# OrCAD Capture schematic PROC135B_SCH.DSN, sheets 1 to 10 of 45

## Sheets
1 03. LINKS TO KEY COLLATERS: title: LINKS TO KEY COLLATERALS AND FAQs; rev: B
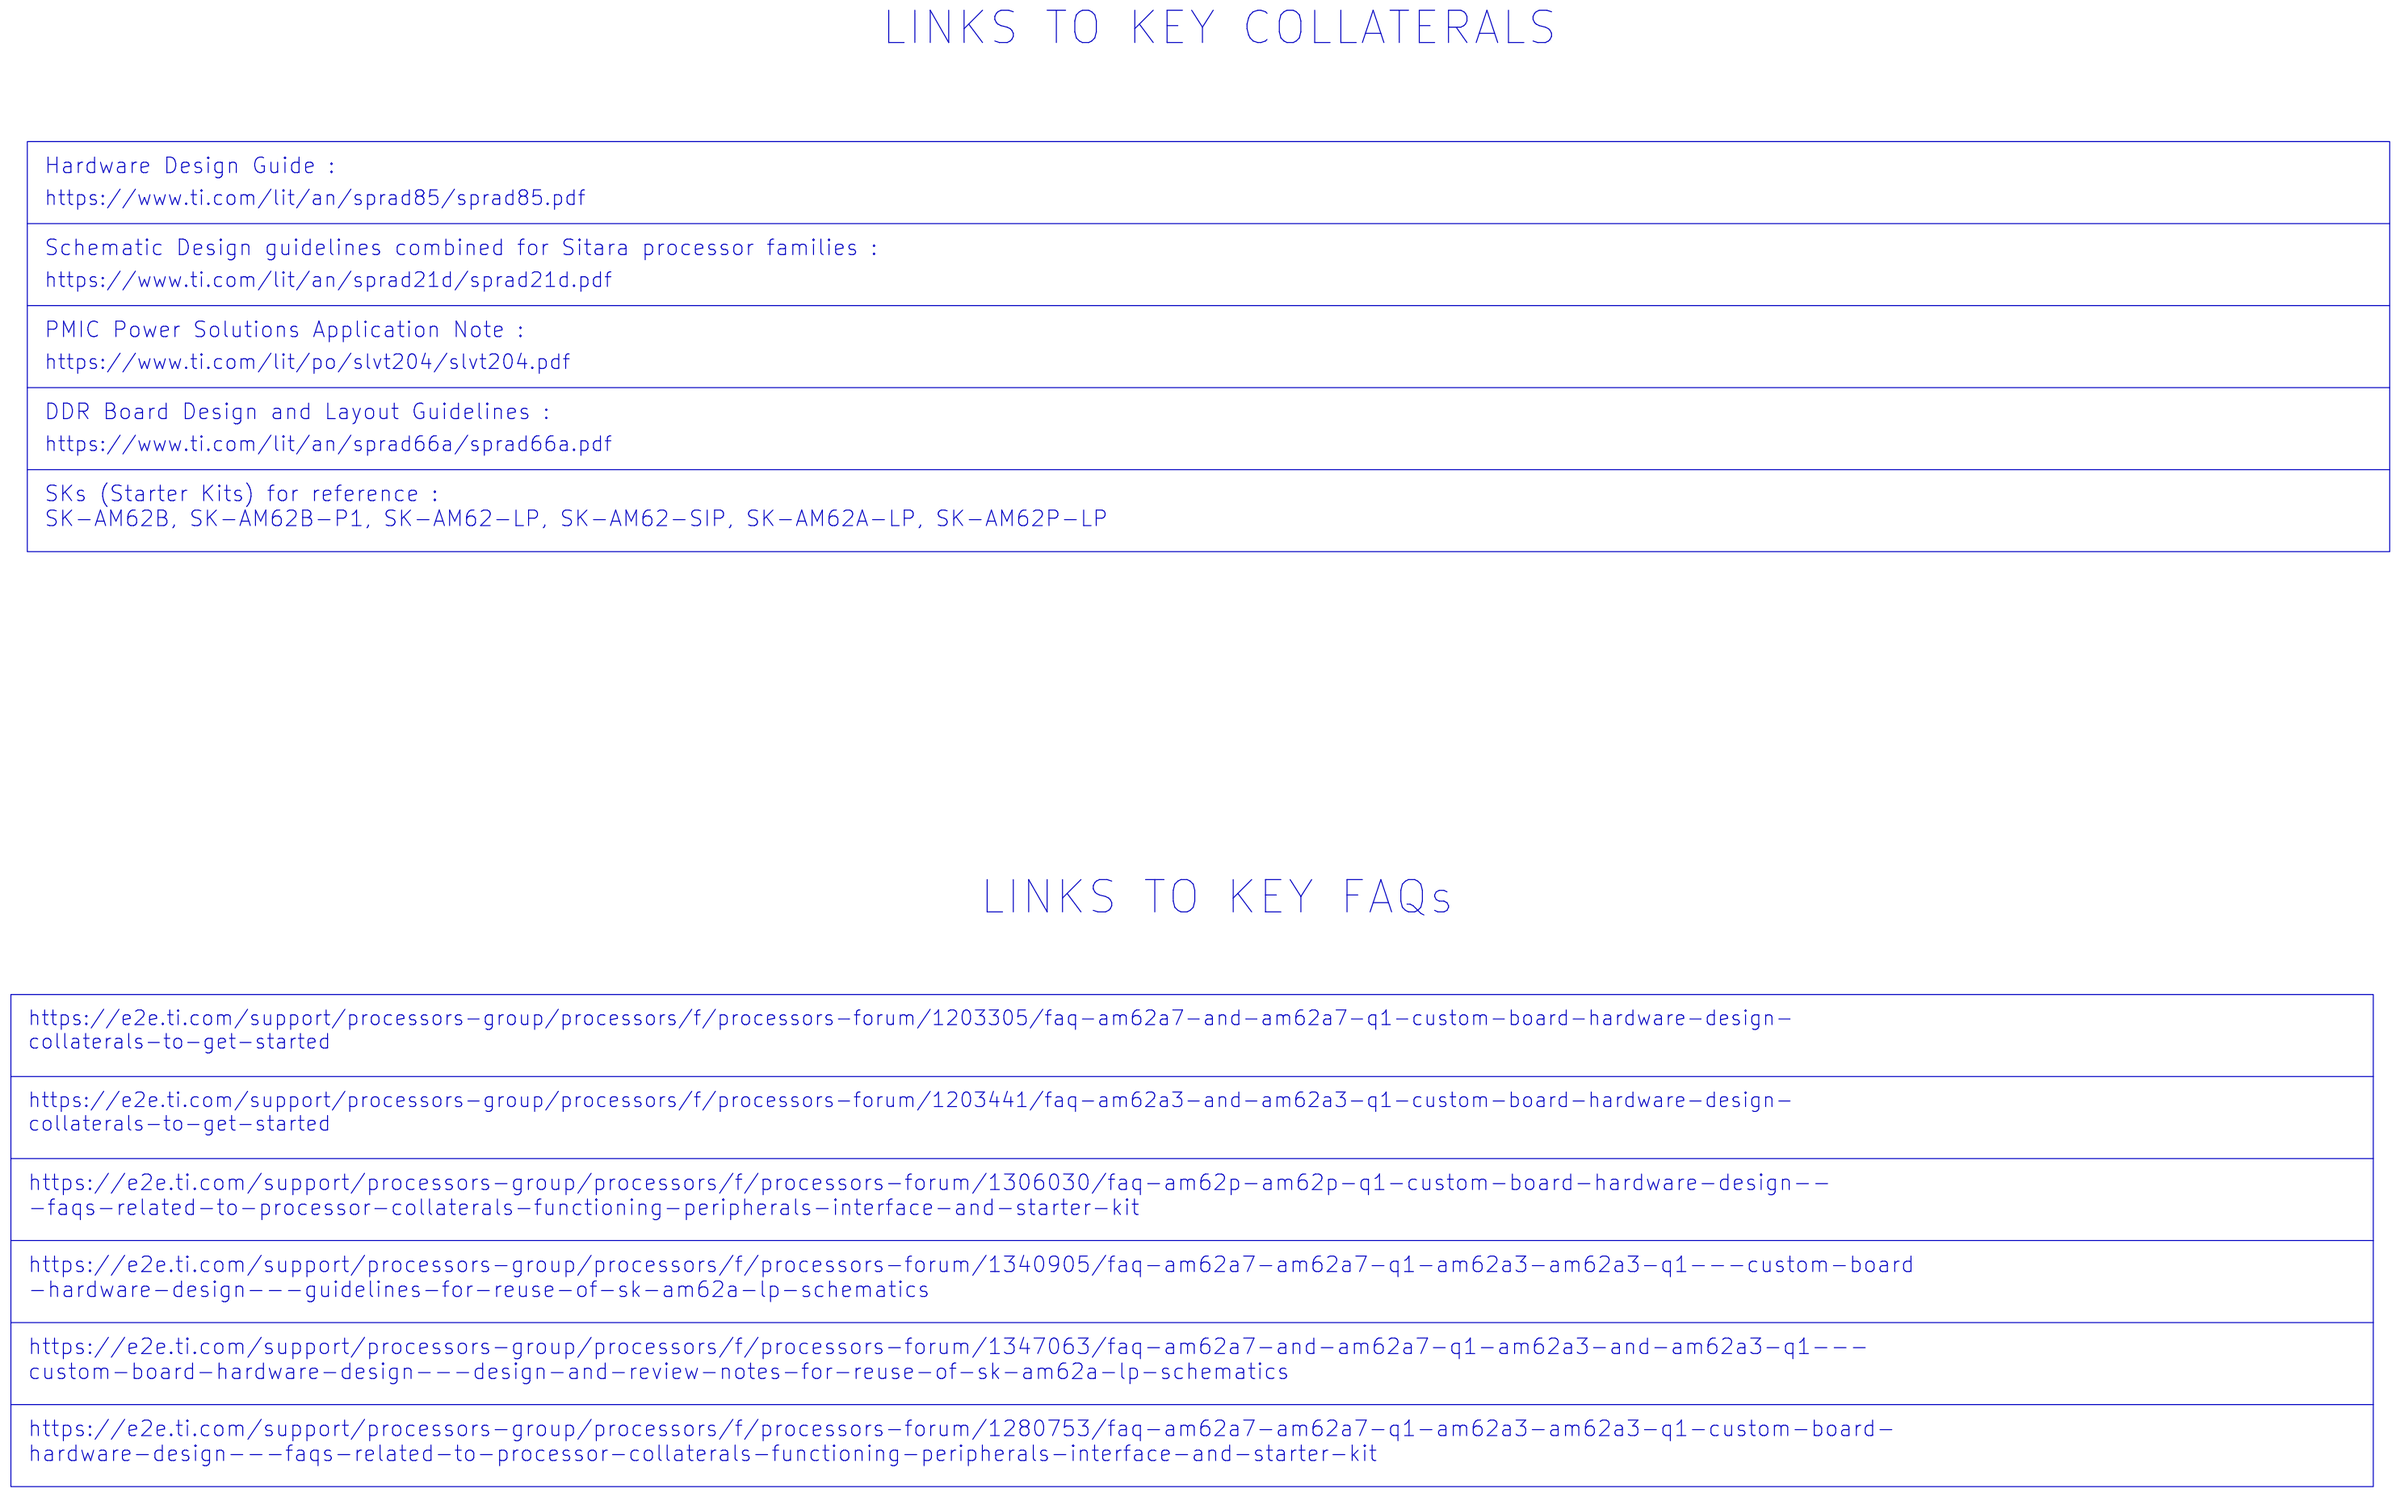
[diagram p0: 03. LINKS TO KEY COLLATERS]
2 01. TABLE OF CONTENTS: title: TABLE OF CONTENTS
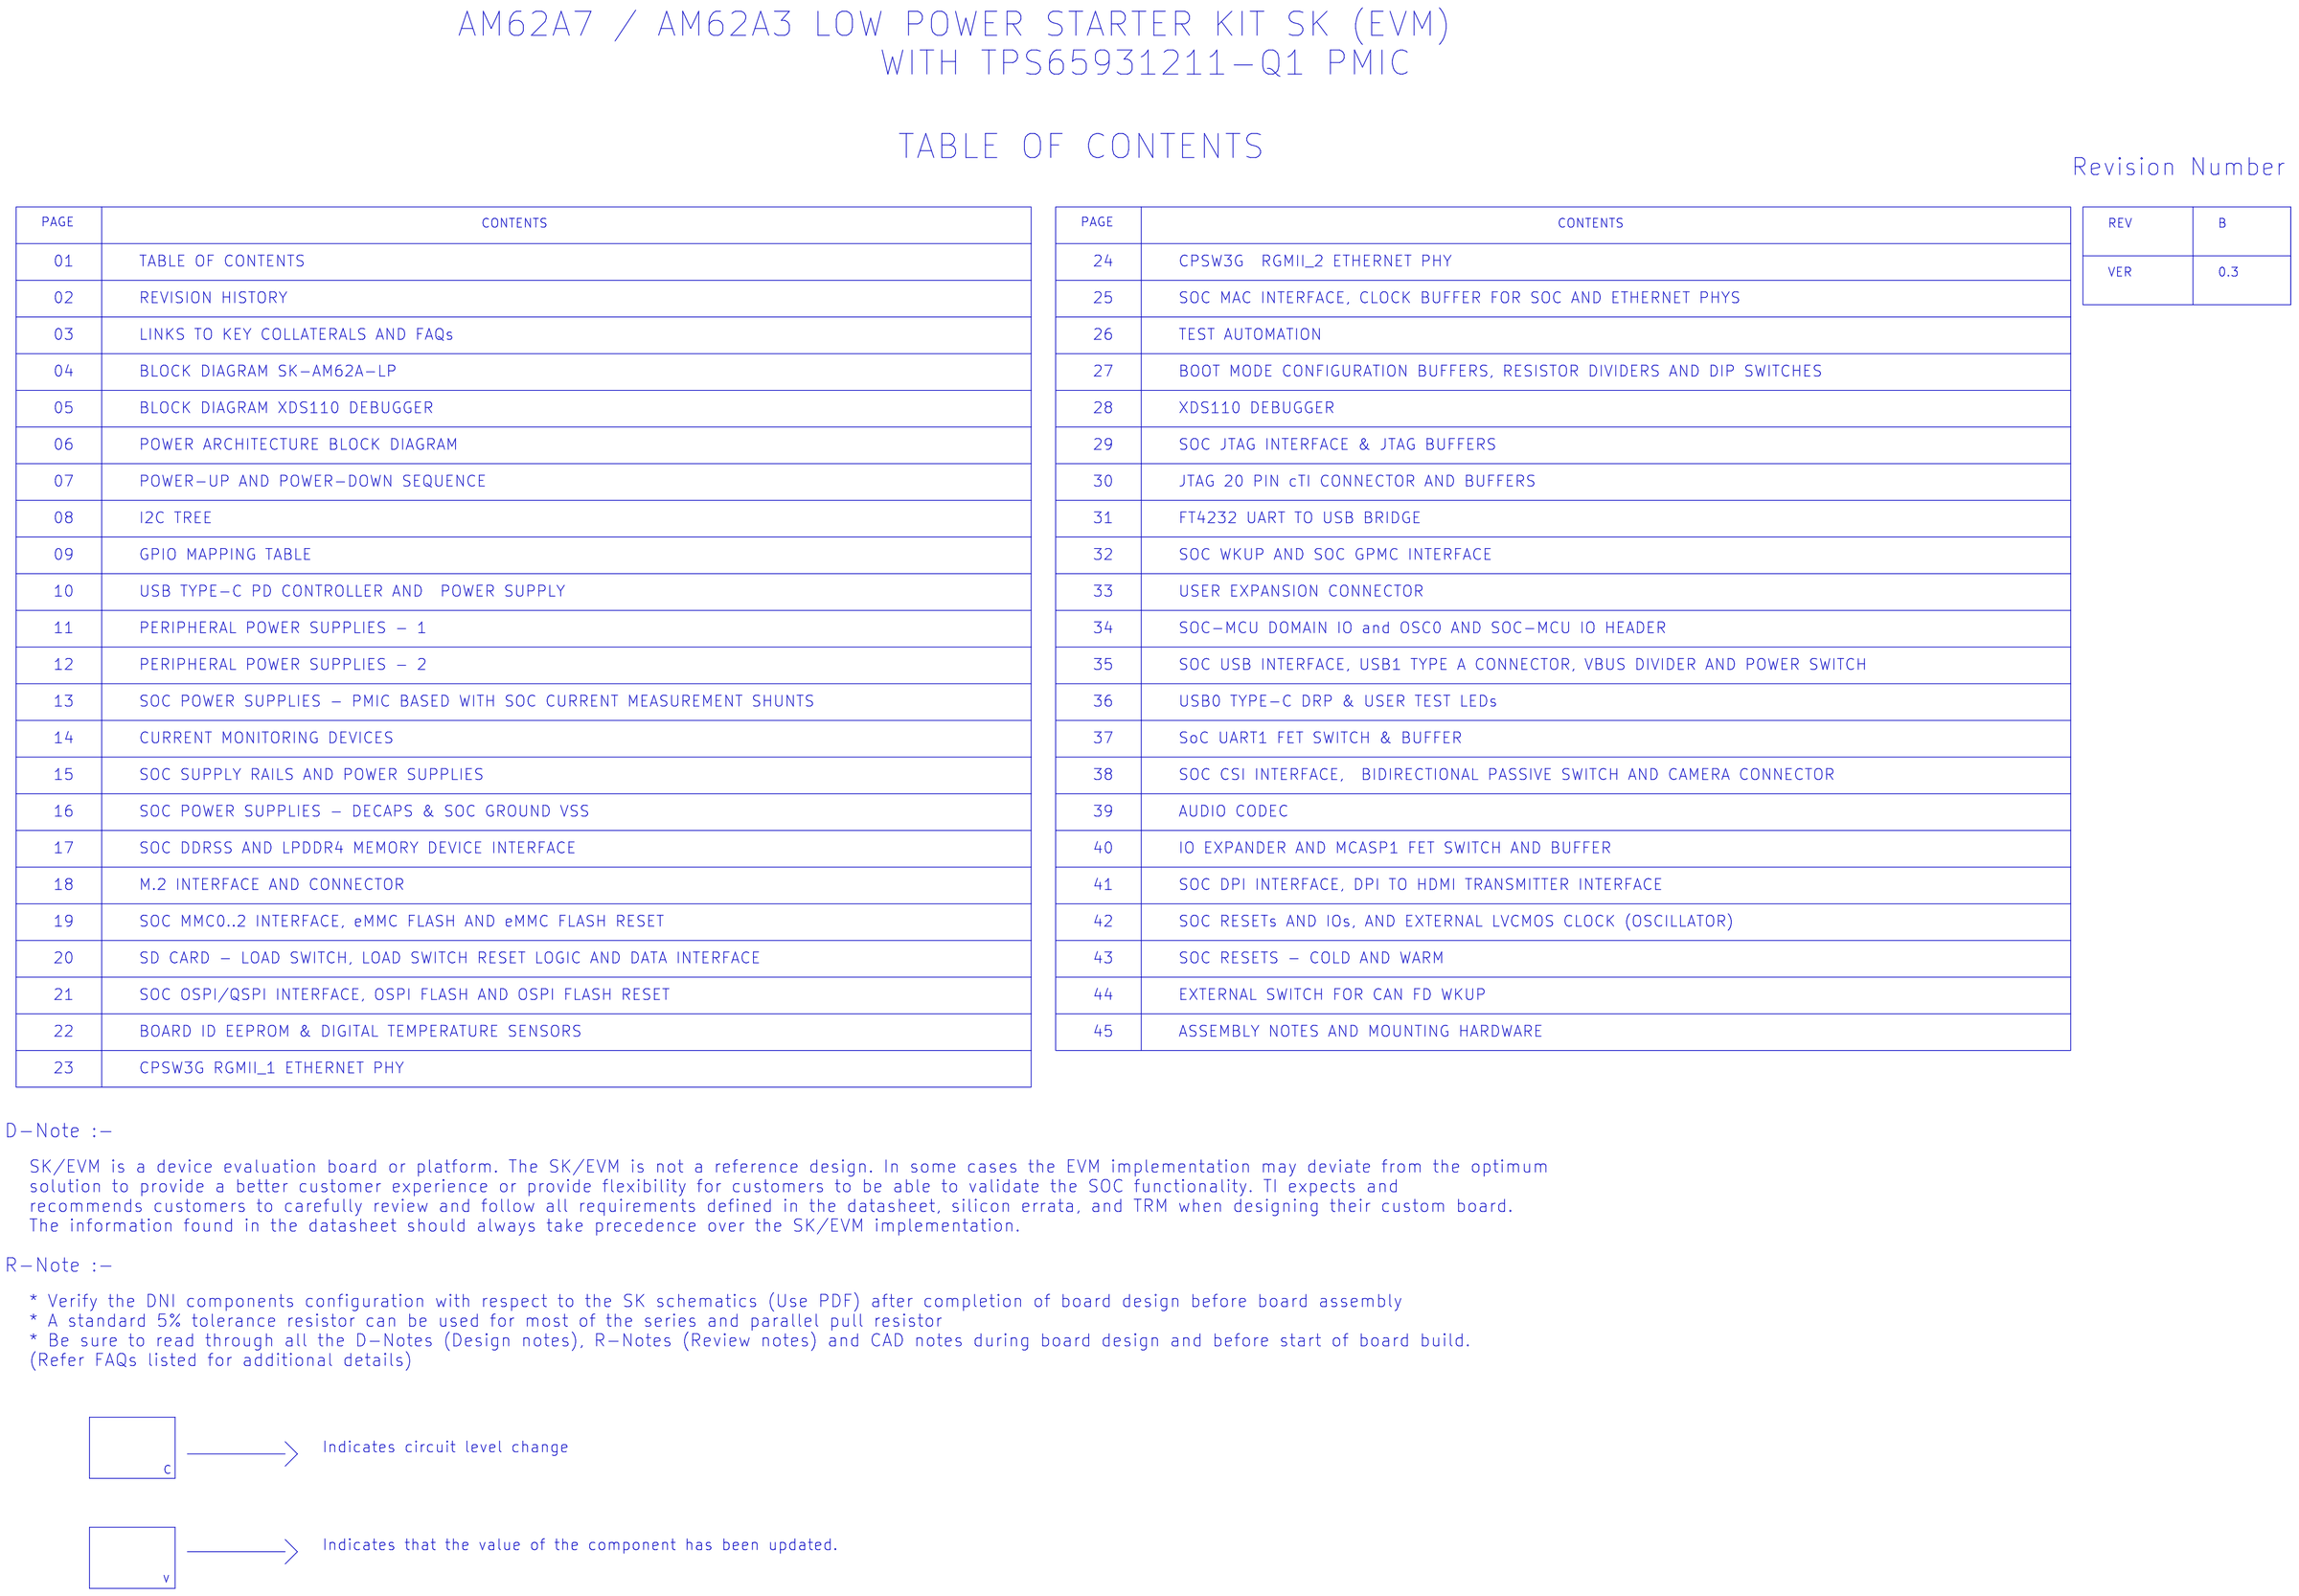
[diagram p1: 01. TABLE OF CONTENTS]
3 02. REVISION HISTORY: title: REVISION HISTORY
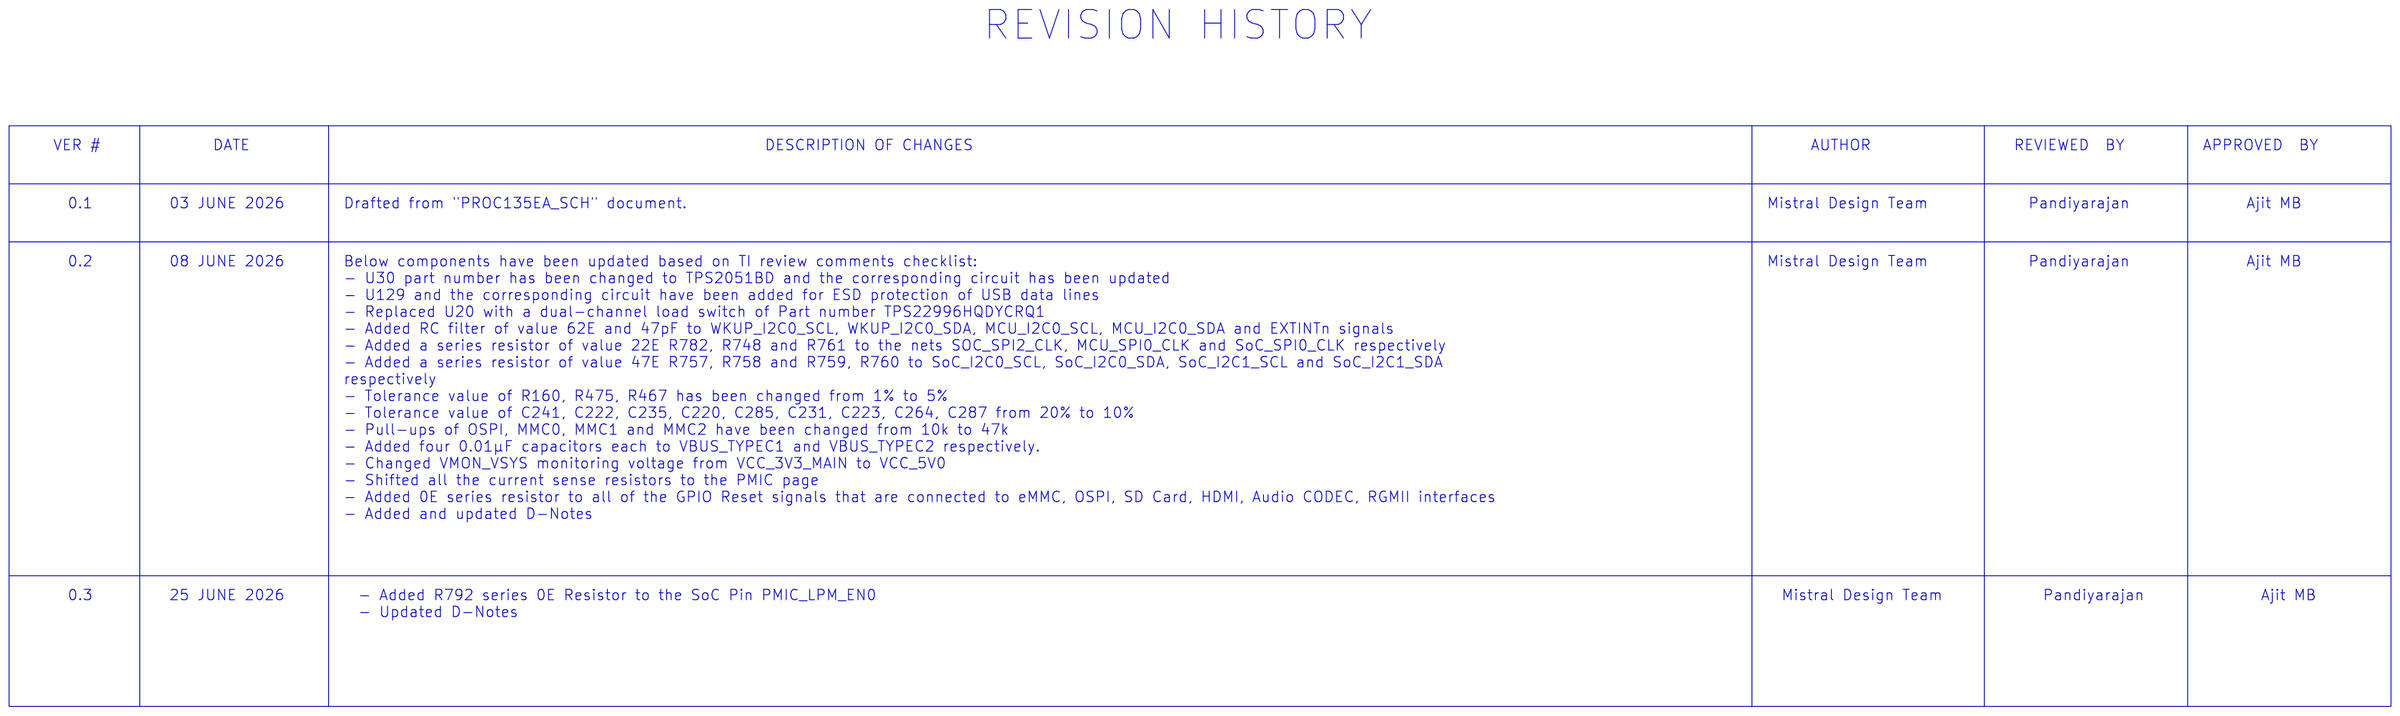
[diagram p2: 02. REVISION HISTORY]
4 04. BLOCK DGM AM62A-SKEVM: title: BLOCK DIAGRAM AM62A_ SKEVM
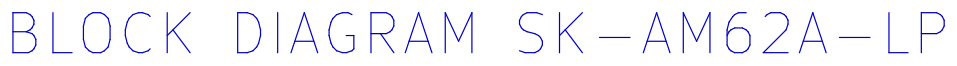
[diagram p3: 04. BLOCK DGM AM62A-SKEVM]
5 05. BLOCK DIAGRAM_XDS110: title: BLOCK DIAGRAM XDS110 DEBUGGER
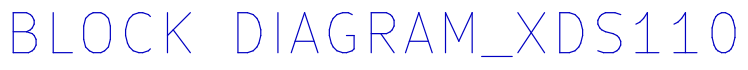
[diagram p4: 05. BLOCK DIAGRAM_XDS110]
6 06. POWER BLOCK DGM: title: POWER ARCHITECTURE BLOCK DIAGRAM
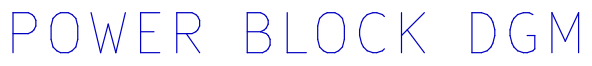
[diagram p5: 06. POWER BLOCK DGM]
7 07. POWER SEQUENCE: title: POWER SEQUENCE
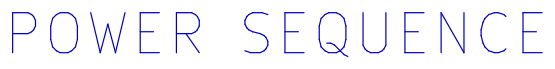
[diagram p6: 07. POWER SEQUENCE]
8 08. I2C TREE: title: I2C TREE
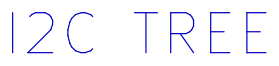
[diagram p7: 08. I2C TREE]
9 09. GPIO MAPPING TABLE: title: GPIO MAPPING TABLE
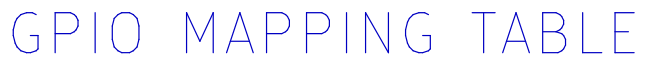
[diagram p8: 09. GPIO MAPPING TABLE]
10 10. USB TYPE-C POWER: size C; title: USB TYPE-C PD CONTROLLER AND  POWER SUPPLY
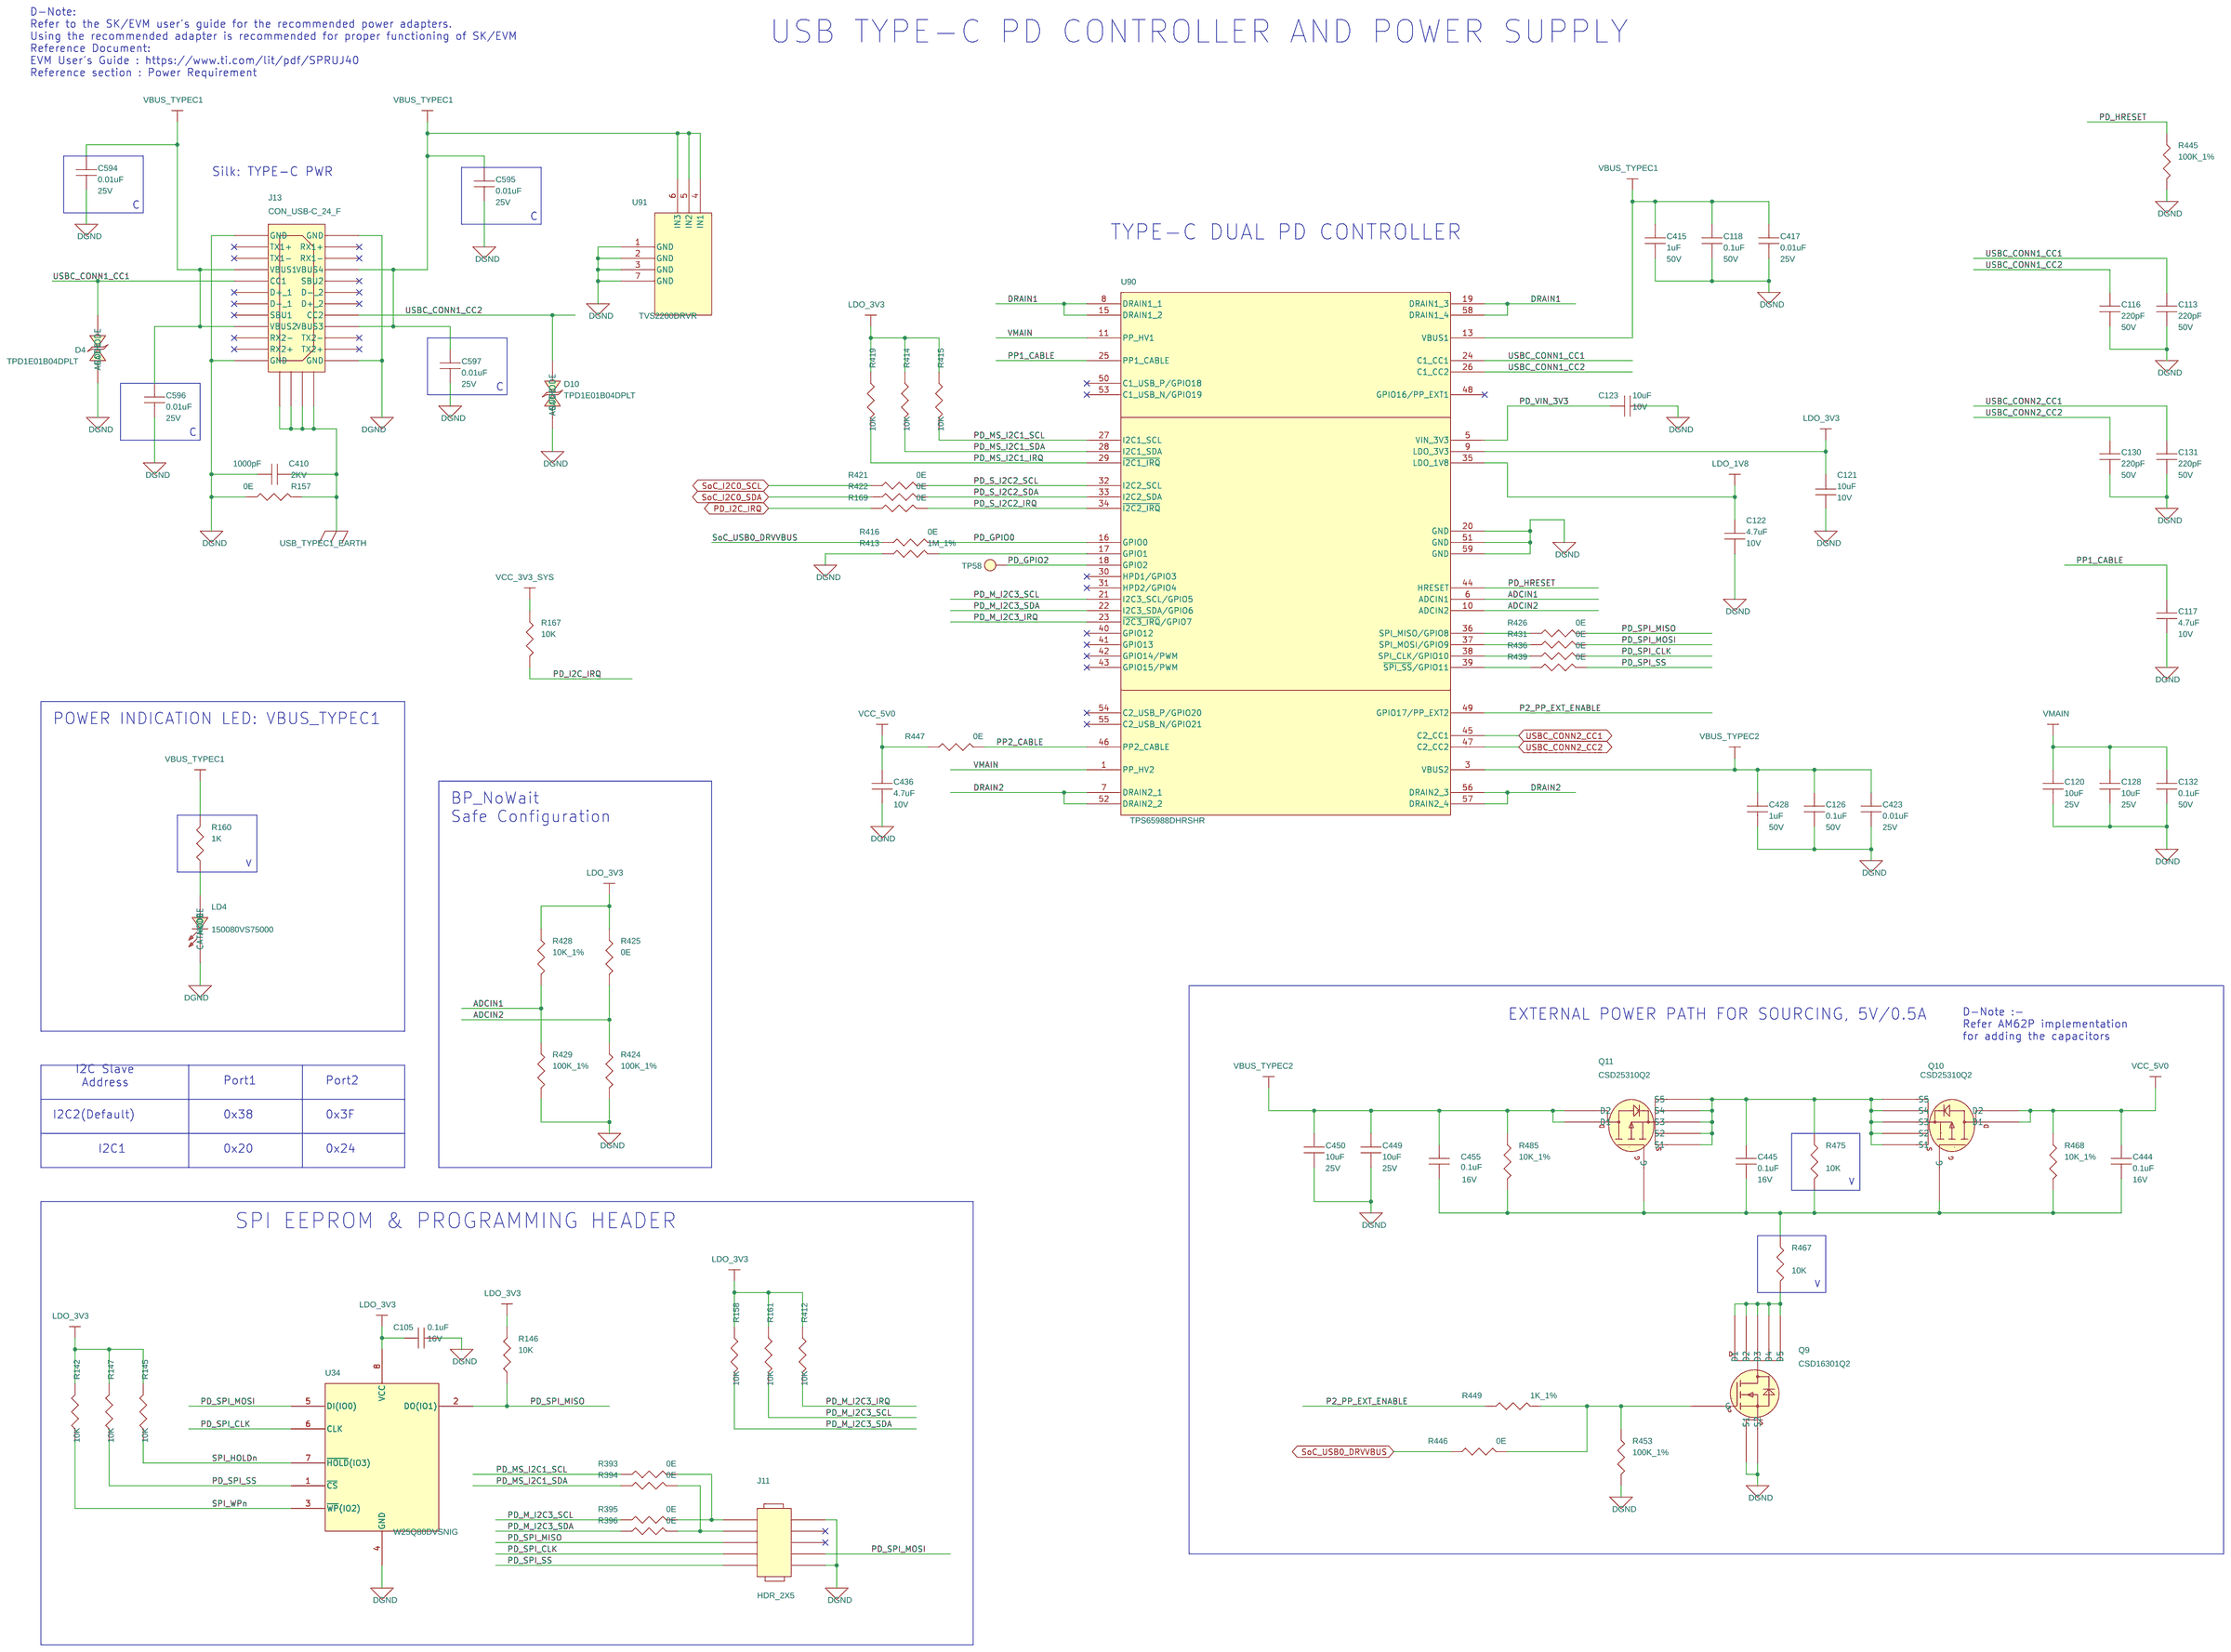
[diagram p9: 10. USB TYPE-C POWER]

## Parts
C105  0.1uF  [CAP0201_0-5]
C113  220pF  [CAP0402_0-75]
C116  220pF  [CAP0402_0-75]
C117  4.7uF  [CAP0402_0-75]
C118  0.1uF  [CAP0402_0-75]
C120  10uF  [CAP0603_1]
C121  10uF  [CAP0402_0-75]
C122  4.7uF  [CAP0402_0-75]
C123  10uF  [CAP0402_0-75]
C126  0.1uF  [CAP0402_0-75]
C128  10uF  [CAP0603_1]
C130  220pF  [CAP0402_0-75]
C131  220pF  [CAP0402_0-75]
C132  0.1uF  [CAP0402_0-75]
C410  1000pF  [CAP1206_1-75]
C415  1uF  [CAP0805_1-5]
C417  0.01uF  [CAP0201_0-5]
C423  0.01uF  [CAP0201_0-5]
C428  1uF  [CAP0805_1-5]
C436  4.7uF  [CAP0402_0-75]
C444  0.1uF  [CAP0201_0-5]
C445  0.1uF  [CAP0201_0-5]
C449  10uF  [CAP0603_1]
C450  10uF  [CAP0603_1]
C455  0.1uF  [CAP0201_0-5]
C594  0.01uF  [CAP0201_0-5]
C595  0.01uF  [CAP0201_0-5]
C596  0.01uF  [CAP0201_0-5]
C597  0.01uF  [CAP0201_0-5]
D4  TPD1E01B04DPLT  [DIO_DFN0201_0-4]
D10  TPD1E01B04DPLT  [DIO_DFN0201_0-4]
J11  HDR_2X5  [HDR_2X5_PEC05DAAN_S_T_8-6]
J13  CON_USB-C_24_F  [CON_USBC24_2012670_S_R_S_3-9]
LD4  150080VS75000  [LED_150080VS75000_80X50_SMD_0-8]
Q9  CSD16301Q2  [WSON6_CSD13202Q2_80X80_0-8]
Q10  CSD25310Q2  [SON6_CSD17313Q2_80X80]
Q11  CSD25310Q2  [SON6_CSD17313Q2_80X80]
R142  10K  [RES0201_0-5]
R145  10K  [RES0201_0-5]
R146  10K  [RES0201_0-5]
R147  10K  [RES0201_0-5]
R157  0E  [RES0603_0-75]
R158  10K  [RES0201_0-5]
R160  1K  [RES0402_0-5]
R161  10K  [RES0201_0-5]
R167  10K  [RES0201_0-5]
R169  0E  [RES0201_0-5]
R393  0E  [RES0201_0-5]
R394  0E  [RES0201_0-5]
R395  0E  [RES0201_0-5]
R396  0E  [RES0201_0-5]
R412  10K  [RES0201_0-5]
R413  1M_1%  [RES0402_0-5]
R414  10K  [RES0201_0-5]
R415  10K  [RES0201_0-5]
R416  0E  [RES0201_0-5]
R419  10K  [RES0201_0-5]
R421  0E  [RES0201_0-5]
R422  0E  [RES0201_0-5]
R424  100K_1%  [RES0402_0-5]
R425  0E  [RES0201_0-5]
R426  0E  [RES0201_0-5]
R428  10K_1%  [RES0201_0-5]
R429  100K_1%  [RES0402_0-5]
R431  0E  [RES0201_0-5]
R436  0E  [RES0201_0-5]
R439  0E  [RES0201_0-5]
R445  100K_1%  [RES0201_0-5]
R446  0E  [RES0201_0-5]
R447  0E  [RES0402_0-5]
R449  1K_1%  [RES0402_0-5]
R453  100K_1%  [RES0402_0-5]
R467  10K  [RES0201_0-5]
R468  10K_1%  [RES0201_0-5]
R475  10K  [RES0201_0-5]
R485  10K_1%  [RES0201_0-5]
TP58  TP20_SMD  [TP20_SMD]
U34  W25Q80DVSNIG  [SOIC8_1-8]
U90  TPS65988DHRSHR  [VQFN56_TPS65987D_280X280_1]
U91  TVS2200DRVR  [SON6_25-59_85X85_0-8]

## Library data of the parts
C105 C444 C445 C455 = CAP: CAP CERAMIC 0.1uF 16V 10% X5R 0201; Chkd/date: PRADEEP/130623; Crtd /date: PRADEEP/130623; Custom_Duty: 15%; Customs_HS_Code: 85322990; Distributor_name: NA; Distributor_part_number: NA; Footprint Path: Y:\MIS_DATABASE\Library\ALTIUM_TOOL\PCB_FOOTPRINTS\Altium_Footprint_Lib.PcbLib; Height: 0.33MM; Library Path: Y:\MIS_DATABASE\Library\ALTIUM_TOOL\SCHEMATICS_PARTS\MS_DISCRETE_Library.schlib; Mfr_name: MURATA; Mfr_part_number: GRT033R61C104KE01; Mistral Part No: 120022060019-R; Package: 0201; Part_type: CAPACITORS\CERAMIC; Project: AM62P_SK; RoHS: RoHS; Temperature: -55°C+85°C; Tolerance: 10%; Voltage: 16V; Wattage: NA; Weight: 0.33mg; Datasheet: Y:\MIS_DATABASE\DATASHEETS\CAPACITORS\GRT033R61C104KE01XX.PDF
C113 C116 C130 C131 = CAP: CAP CERAMIC 220pF 50V 5% C0G(NP0) AUTO 0402; Chkd/date: PRADEEP/130623; Crtd /date: PRADEEP/130623; Custom_Duty: 15%; Customs_HS_Code: 85322990; Distributor_name: NA; Distributor_part_number: NA; Footprint Path: Y:\MIS_DATABASE\Library\ALTIUM_TOOL\PCB_FOOTPRINTS\Altium_Footprint_Lib.PcbLib; Height: 0.55MM; Library Path: Y:\MIS_DATABASE\Library\ALTIUM_TOOL\SCHEMATICS_PARTS\MS_DISCRETE_Library.schlib; Mfr_name: MURATA; Mfr_part_number: GRT1555C1H221JA02; Mistral Part No: 120022060024-R; Package: 0402; Part_type: CAPACITORS\CERAMIC; Project: AM62P_SK; RoHS: RoHS; Temperature: -55°C+125°C; Tolerance: 5%; Voltage: 50V; Wattage: NA; Weight: 3.1mg; Datasheet: Y:\MIS_DATABASE\DATASHEETS\CAPACITORS\GRT1555C1H221JA02.PDF
C117 C122 C436 = CAP: CAP CERAMIC 4.7uF 10V 20% X5R AUTO 0402; Chkd/date: MANIRAJA/250221; Crtd /date: ALVY/240221; Custom_Duty: 15%; Customs_HS_Code: 85322990; Distributor_name: MOUSER; Distributor_part_number: 81-GRT155R61A475ME13; Footprint Path: Y:\MIS_DATABASE\Library\ALTIUM_TOOL\PCB_FOOTPRINTS\Altium_Footprint_Lib.PcbLib; Height: 0.65MM; Library Path: Y:\MIS_DATABASE\Library\ALTIUM_TOOL\SCHEMATICS_PARTS\MS_DISCRETE_Library.schlib; Mfr_name: MURATA; Mfr_part_number: GRT155R61A475ME13D; Mistral Part No: 120021020032-R; Package: 0402; Part_type: CAPACITORS\CERAMIC; Project: TI_DRA821 SK EVM BRD; RoHS: RoHS; Temperature: -55°C+85°C; Tolerance: 20%; Voltage: 10V; Wattage: NA; Weight: 1.5mg; Datasheet: Y:\MIS_DATABASE\DATASHEETS\CAPACITORS\GRT155R61A475ME13.PDF
C118 C126 C132 = CAP: CAP CERAMIC 0.1uF 50V 10% X7R AUTO 0402; Chkd/date: MANIRAJA/250221; Crtd /date: ALVY/240221; Custom_Duty: 15%; Customs_HS_Code: 85322990; Distributor_name: MOUSER; Distributor_part_number: 81-GRT155R71H104KE1D; Footprint Path: Y:\MIS_DATABASE\Library\ALTIUM_TOOL\PCB_FOOTPRINTS\Altium_Footprint_Lib.PcbLib; Height: 0.55MM; Library Path: Y:\MIS_DATABASE\Library\ALTIUM_TOOL\SCHEMATICS_PARTS\MS_DISCRETE_Library.schlib; Mfr_name: MURATA; Mfr_part_number: GRT155R71H104KE01D; Mistral Part No: 120019030005-R; Package: 0402; Part_type: CAPACITORS\CERAMIC; Project: TI_DRA821 SK EVM BRD; RoHS: RoHS; Temperature: -55°C+125°C; Tolerance: 10%; Voltage: 50V; Wattage: NA; Weight: NA; Datasheet: Y:\MIS_DATABASE\DATASHEETS\CAPACITORS\GRT155R71H104KE01.PDF
C120 C128 C449 C450 = CAP: CAP CERAMIC 10uF 25V 20% X5R AUTO 0603; Chkd/date: PRADEEP/130623; Crtd /date: PRADEEP/130623; Custom_Duty: 15%; Customs_HS_Code: 85322990; Distributor_name: NA; Distributor_part_number: NA; Footprint Path: Y:\MIS_DATABASE\Library\ALTIUM_TOOL\PCB_FOOTPRINTS\Altium_Footprint_Lib.PcbLib; Height: 1.00MM; Library Path: Y:\MIS_DATABASE\Library\ALTIUM_TOOL\SCHEMATICS_PARTS\MS_DISCRETE_Library.schlib; Mfr_name: MURATA; Mfr_part_number: GRT188R61E106ME13; Mistral Part No: 120022060023-R; Package: 0603; Part_type: CAPACITORS\CERAMIC; Project: AM62P_SK; RoHS: RoHS; Temperature: -55°C+85°C; Tolerance: 20%; Voltage: 25V; Wattage: NA; Weight: 2mg; Datasheet: Y:\MIS_DATABASE\DATASHEETS\CAPACITORS\GRT188R61E106ME13.PDF
C121 C123 = CAP: CAP CERAMIC 10uF 10V 20% X5R 0402; Chkd/date: PRADEEP/130623; Crtd /date: PRADEEP/130623; Custom_Duty: 15%; Customs_HS_Code: 85322990; Distributor_name: NA; Distributor_part_number: NA; Footprint Path: Y:\MIS_DATABASE\Library\ALTIUM_TOOL\PCB_FOOTPRINTS\Altium_Footprint_Lib.PcbLib; Height: 0.55MM; Library Path: Y:\MIS_DATABASE\Library\ALTIUM_TOOL\SCHEMATICS_PARTS\MS_DISCRETE_Library.schlib; Mfr_name: MURATA; Mfr_part_number: GRM155R61A106ME18; Mistral Part No: 120022060018-R; Package: 0402; Part_type: CAPACITORS\CERAMIC; Project: AM62P_SK; RoHS: RoHS; Temperature: -55°C+85°C; Tolerance: 20%; Voltage: 10V; Wattage: NA; Weight: 6mg; Datasheet: Y:\MIS_DATABASE\DATASHEETS\CAPACITORS\MURATA-GXX-SER_NOV17.PDF
C410 = CAP: CAP CERAMIC 1000pF 2KV 10% X7R 1206; Chkd/date: SHREESHAIL/291106; Crtd /date: MAZHAR/281106; Custom_Duty: 15%; Customs_HS_Code: 85322990; Distributor_name: DIGIKEY; Distributor_part_number: 478-2956-1-ND; Footprint Path: Y:\MIS_DATABASE\Library\ALTIUM_TOOL\PCB_FOOTPRINTS\Altium_Footprint_Lib.PcbLib; Height: 1.52MM; Library Path: Y:\MIS_DATABASE\Library\ALTIUM_TOOL\SCHEMATICS_PARTS\MS_DISCRETE_Library.schlib; Mfr_name: AVX CORPORATION; Mfr_part_number: 1206GC102KAT1A; Mistral Part No: 120015080006-R; Package: 1206; Part_type: CAPACITORS\CERAMIC; Project: ADR1B; RoHS: RoHS; Temperature: -55°C+125°C; Tolerance: 10%; Voltage: 2KV; Wattage: NA; Weight: 16.2mg; Datasheet: Y:\MIS_DATABASE\DATASHEETS\CAPACITORS\AVX_HV-MLC.PDF
C415 C428 = CAP: CAP CERAMIC 1uF 50V 10% X7R AUTO 0805; Chkd/date: MANIRAJA/250221; Crtd /date: ALVY/240221; Custom_Duty: 15%; Customs_HS_Code: 85322990; Distributor_name: MOUSER; Distributor_part_number: 81-GRT21BR71H105KE1L; Footprint Path: Y:\MIS_DATABASE\Library\ALTIUM_TOOL\PCB_FOOTPRINTS\Altium_Footprint_Lib.PcbLib; Height: 1.35MM; Library Path: Y:\MIS_DATABASE\Library\ALTIUM_TOOL\SCHEMATICS_PARTS\MS_DISCRETE_Library.schlib; Mfr_name: MURATA; Mfr_part_number: GRT21BR71H105KE01L; Mistral Part No: 120021020035-R; Package: 0805; Part_type: CAPACITORS\CERAMIC; Project: TI_DRA821 SK EVM BRD; RoHS: RoHS; Temperature: -55°C+125°C; Tolerance: 10%; Voltage: 50V; Wattage: NA; Weight: 17mg; Datasheet: Y:\MIS_DATABASE\DATASHEETS\CAPACITORS\GRT21BR71H105KE01.PDF
C417 C423 C594-C597 = CAP: CAP CERAMIC 0.01uF 25V 10% X5R AUTO 0201; Chkd/date: MANIRAJA/311221; Crtd /date: ALVY/301221; Custom_Duty: 15%; Customs_HS_Code: 85322990; Distributor_name: MOUSER; Distributor_part_number: 81-GRT033R61E103KE1D; Footprint Path: Y:\MIS_DATABASE\Library\ALTIUM_TOOL\PCB_FOOTPRINTS\Altium_Footprint_Lib.PcbLib; Height: 0.33MM; Library Path: Y:\MIS_DATABASE\Library\ALTIUM_TOOL\SCHEMATICS_PARTS\MS_DISCRETE_Library.schlib; Mfr_name: MURATA; Mfr_part_number: GRT033R61E103KE01D; Mistral Part No: 120021120019-R; Package: 0201; Part_type: CAPACITORS\CERAMIC; Project: AM62Q_SKEVM_BRD; RoHS: RoHS; Temperature: -55°C+85°C; Tolerance: 10%; Voltage: 25V; Wattage: NA; Weight: 0.33mg; Datasheet: Y:\MIS_DATABASE\DATASHEETS\CAPACITORS\GRT033R61E103KE01.PDF
D4 D10 = DIODE_TVS_DUAL: DIODE 1CH ESD PROTECTION FOR USB TYPE-C AND THUNDERBOLT3 X2SON2; Chkd/date: MANIRAJA/230920; Crtd /date: ALVY/230920; Custom_Duty: 15%; Customs_HS_Code: 85412900; Distributor_name: DIGIKEY; Distributor_part_number: 296-44484-1-ND; Footprint Path: Y:\MIS_DATABASE\Library\ALTIUM_TOOL\PCB_FOOTPRINTS\Altium_Footprint_Lib.PcbLib; Height: 0.32MM; Library Path: Y:\MIS_DATABASE\Library\ALTIUM_TOOL\SCHEMATICS_PARTS\MS_DISCRETE_Library.schlib; Mfr_name: TEXAS INSTRUMENTS; Mistral Part No: 130020090037-R; Package: X2SON2; Part_type: DIODE\TVS; Project: AM64X_SKEVM; RoHS: RoHS; Temperature: -40°C+125°C; Tolerance: NA; Voltage: NA; Wattage: NA; Weight: 0.2mg; Datasheet: Y:\MIS_DATABASE\DATASHEETS\DISCRETES\DIODES\TPD1E01B04.PDF
J11 = HEADER_5X2: CON HDR 2X5 2.54MM PITCH ST TH; Chkd/date: MANIRAJA/060821; Crtd /date: ALVY/060821; Custom_Duty: 24%; Customs_HS_Code: 85369090; Distributor_name: DIGIKEY; Distributor_part_number: S2012E-05-ND; Footprint Path: Y:\MIS_DATABASE\Library\ALTIUM_TOOL\PCB_FOOTPRINTS\Altium_Footprint_Lib.PcbLib; Height: 8.58MM; Library Path: Y:\MIS_DATABASE\Library\ALTIUM_TOOL\SCHEMATICS_PARTS\MS_CONNECTOR_Library.schlib; Mfr_name: SULLINS CONNECTOR; Mfr_part_number: PEC05DAAN; Mistral Part No: 150021080010-R; Package: THRU-HOLE; Part_type: CONNECTOR\HEADERS; Project: TI_AM335x SK_BRD; RoHS: RoHS; Temperature: -65°C+125°C; Tolerance: NA; Voltage: NA; Wattage: NA; Weight: NA; Datasheet: Y:\MIS_DATABASE\DATASHEETS\CONNECTORS\XXCXXDXXN.PDF
J13 = CON_USB-C_24_1240183621: CON USB-C TYPE 24POS FEMALE RT SMD; Chkd/date: MANIRAJA/050618; Crtd /date: ALVY/040618; Custom_Duty: 24%; Customs_HS_Code: 85369090; Distributor_name: DIGIKEY; Distributor_part_number: WM17992CT-ND; Footprint Path: Y:\MIS_DATABASE\Library\ALTIUM_TOOL\PCB_FOOTPRINTS\Altium_Footprint_Lib.PcbLib; Height: 3.86MM; Library Path: Y:\MIS_DATABASE\Library\ALTIUM_TOOL\SCHEMATICS_PARTS\MS_CONNECTOR_Library.schlib; Mfr_name: MOLEX; Mfr_part_number: 2012670005; Mistral Part No: 150018060002-R; Package: SMD; Part_type: CONNECTOR\USB; Project: TI_J7SVB_USB_ADD-ON-CARD; RoHS: RoHS; Temperature: -40°C+105°C; Tolerance: NA; Voltage: NA; Wattage: NA; Weight: 0.686g; Datasheet: Y:\MIS_DATABASE\DATASHEETS\CONNECTORS\2012670X.PDF
LD4 = DIODE_LED: DIODE LED BRIGHT GREEN SMD; Chkd/date: MANIRAJA/180820; Crtd /date: ALVY/180820; Custom_Duty: 24%; Customs_HS_Code: 85439000; Distributor_name: DIGIKEY; Distributor_part_number: 732-4986-1-ND; Footprint Path: Y:\MIS_DATABASE\Library\ALTIUM_TOOL\PCB_FOOTPRINTS\Altium_Footprint_Lib.PcbLib; Height: 0.80MM; Library Path: Y:\MIS_DATABASE\Library\ALTIUM_TOOL\SCHEMATICS_PARTS\MS_OPTO_Library.schlib; Mfr_name: WURTH ELECTRONICS; Mistral Part No: 130020080012-R; Package: SMD; Part_type: OPTO\LED; Project: AM64x_EVM_BRD; RoHS: RoHS; Temperature: -40°C+85°C; Tolerance: NA; Voltage: NA; Wattage: NA; Weight: 10mg; Datasheet: Y:\MIS_DATABASE\DATASHEETS\DISCRETES\LEDS\150080VS75000.PDF
Q9 = MOSFET_CSD17313Q2: IC MOSFET N-CHANNEL NEXFET 25V WSON6; Chkd/date: ALVY/071220; Crtd /date: MANIRAJA/071220; Custom_Duty: 15%; Customs_HS_Code: 85423100; Distributor_name: DIGIKEY; Distributor_part_number: 296-25260-1-ND; Footprint Path: Y:\MIS_DATABASE\Library\ALTIUM_TOOL\PCB_FOOTPRINTS\Altium_Footprint_Lib.PcbLib; Height: 0.80MM; Library Path: Y:\MIS_DATABASE\Library\ALTIUM_TOOL\SCHEMATICS_PARTS\MS_MOSFET_Library.schlib; Mfr_name: TEXAS INSTRUMENTS; Mistral Part No: 142020120008-R; Package: WSON6; Part_type: ICS\POWER\MOSFET; Project: TI_AM243x LP EVM; RoHS: RoHS; Temperature: -55°C+150°C; Tolerance: NA; Voltage: NA; Wattage: NA; Weight: 8.7mg; Datasheet: Y:\MIS_DATABASE\DATASHEETS\ICS\POWER\CSD16301Q2.PDF
Q10 Q11 = MOSFET_CSD25310Q2: IC MOSFET P-CHANNEL WSON6; Chkd/date: VASANTHA/191215; Crtd /date: VASANTHA/191215; Custom_Duty: 15%; Customs_HS_Code: 85423100; Distributor_name: DIGIKEY; Distributor_part_number: 296-38915-1-ND; Height: 0.85MM; Mfr_name: TEXAS INSTRUMENTS; Mistral Part No: 142015120011-R; Package: WSON6; Part_type: ICS\POWER\MOSFET; Project: DUET BOARD; RoHS: RoHS; Temperature: -55°C+150°C; Tolerance: NA; Voltage: NA; Wattage: NA; Weight: NA; Datasheet: Y:\MIS_DATABASE\DATASHEETS\DISCRETES\TRANSISTORS_FETS\CSD25310Q2.PDF
R142 R145-R147 R158 R161 R167 R412 R414 R415 R419 R467 R475 = RESISTOR: RES 10K 1/20W 5% 0201; Chkd/date: MANIRAJA/050517; Crtd /date: MANIRAJA/050517; Custom_Duty: 15%; Customs_HS_Code: 85332119; Distributor_name: DIGIKEY; Distributor_part_number: 311-10KNCT-ND; Footprint Path: Y:\MIS_DATABASE\Library\ALTIUM_TOOL\PCB_FOOTPRINTS\Altium_Footprint_Lib.PcbLib; Height: 0.26MM; Library Path: Y:\MIS_DATABASE\Library\ALTIUM_TOOL\SCHEMATICS_PARTS\MS_DISCRETE_Library.schlib; Mfr_name: YAGEO AMERICA; Mfr_part_number: RC0201JR-0710KL; Mistral Part No: 110010070051-R; Package: 0201; Part_type: RESISTORS\FIXED; Project: GOLDEN-I LITE; RoHS: RoHS; Temperature: -55°C+125°C; Tolerance: 5%; Voltage: NA; Wattage: 1/20W; Weight: 0.17mg; Datasheet: Y:\MIS_DATABASE\DATASHEETS\RESISTORS\RCXXXXL-SER_MAR18.PDF
R157 = RESISTOR: RES 0E 1/10W 5% 0603; Chkd/date: MANIRAJA/051217; Crtd /date: BAVISH/180211; Custom_Duty: 15%; Customs_HS_Code: 85332119; Distributor_name: DIGIKEY; Distributor_part_number: 311-0.0GRCT-ND; Footprint Path: Y:\MIS_DATABASE\Library\ALTIUM_TOOL\PCB_FOOTPRINTS\Altium_Footprint_Lib.PcbLib; Height: 0.55MM; Library Path: Y:\MIS_DATABASE\Library\ALTIUM_TOOL\SCHEMATICS_PARTS\MS_DISCRETE_Library.schlib; Manufacturer: YAGEO AMERICA; Mfr_name: PANASONIC-ECG; Mfr_part_number: RC0603JR-070RL; Mistral Part No: 110011020013-R; Package: 0603; Part_type: RESISTORS\FIXED; Project: KENNEL; RoHS: RoHS; Temperature: -55°C+155°C; Tolerance: 5%; Voltage: NA; Wattage: 1/10W; Weight: 2mg; Datasheet: Y:\MIS_DATABASE\DATASHEETS\RESISTORS\RCXXXXL-SER_MAR18.PDF
R160 = RESISTOR: RES 1K 1/10W 5% 0402; Chkd/date: VASANTHA/201216; Crtd /date: MAZHAR/230805; Custom_Duty: 15%; Customs_HS_Code: 85332119; Distributor_name: DIGIKEY; Distributor_part_number: P1.0KJCT-ND; Footprint Path: Y:\MIS_DATABASE\Library\ALTIUM_TOOL\PCB_FOOTPRINTS\Altium_Footprint_Lib.PcbLib; Height: 0.40MM; Library Path: Y:\MIS_DATABASE\Library\ALTIUM_TOOL\SCHEMATICS_PARTS\MS_DISCRETE_Library.schlib; Mfr_name: PANASONIC-ECG; Mfr_part_number: ERJ-2GEJ102X; Mistral Part No: 110009030400-R; Package: 0402; Part_type: RESISTORS\FIXED; Project: HSE; RoHS: RoHS; Temperature: -55°C+155°C; Tolerance: 5%; Voltage: NA; Wattage: 1/10W; Weight: 0.8mg; Datasheet: Y:\MIS_DATABASE\DATASHEETS\RESISTORS\PAN-ERJSER_NOV17.PDF
R169 R393-R396 R416 R421 R422 R426 R431 R436 R439 R446 = RESISTOR: RES 0E 1/20W 5% 0201; Chkd/date: NAVEED/301214; Crtd /date: MUDDU/120710; Custom_Duty: 15%; Customs_HS_Code: 85332119; Distributor_name: DIGIKEY; Distributor_part_number: 311-0.0NCT-ND; Footprint Path: Y:\MIS_DATABASE\Library\ALTIUM_TOOL\PCB_FOOTPRINTS\Altium_Footprint_Lib.PcbLib; Height: 0.26MM; Library Path: Y:\MIS_DATABASE\Library\ALTIUM_TOOL\SCHEMATICS_PARTS\MS_DISCRETE_Library.schlib; Mfr_name: YAGEO AMERICA; Mfr_part_number: RC0201JR-070RL; Mistral Part No: 110010070067-R; Package: 0201; Part_type: RESISTORS\FIXED; Project: PB_BUGBASE; RoHS: RoHS; Temperature: -55°C+125°C; Tolerance: 5%; Voltage: NA; Wattage: 1/20W; Weight: 0.17mg; Datasheet: Y:\MIS_DATABASE\DATASHEETS\RESISTORS\RCXXXXL-SER_MAR18.PDF
R413 = RESISTOR: RES 1M 1/16W 1% 0402; Chkd/date: MANIRAJA/190319; Crtd /date: MANIRAJA/190319; Custom_Duty: 15%; Customs_HS_Code: 85332119; Distributor_name: DIGIKEY; Distributor_part_number: 311-1.00MLRCT-ND; Footprint Path: Y:\MIS_DATABASE\Library\ALTIUM_TOOL\PCB_FOOTPRINTS\Altium_Footprint_Lib.PcbLib; Height: 0.40MM; Library Path: Y:\MIS_DATABASE\Library\ALTIUM_TOOL\SCHEMATICS_PARTS\MS_DISCRETE_Library.schlib; Mfr_name: YAGEO AMERICA; Mfr_part_number: RC0402FR-071ML; Mistral Part No: 110014060045-R; Package: 0402; Part_type: RESISTORS\FIXED; Project: G4SLIM; RoHS: RoHS; Temperature: -55°C+155°C; Tolerance: 1%; Voltage: NA; Wattage: 1/16W; Weight: 0.65mg; Datasheet: Y:\MIS_DATABASE\DATASHEETS\RESISTORS\RCXXXXL-SER_MAR18.PDF
R424 R429 R453 = RESISTOR: RES 100K 1/10W 1% 0402; Chkd/date: VASANTHA/201216; Crtd /date: MAZHAR/130306; Custom_Duty: 15%; Customs_HS_Code: 85332119; Distributor_name: DIGIKEY; Distributor_part_number: P100KLCT-ND; Footprint Path: Y:\MIS_DATABASE\Library\ALTIUM_TOOL\PCB_FOOTPRINTS\Altium_Footprint_Lib.PcbLib; Height: 0.40MM; Library Path: Y:\MIS_DATABASE\Library\ALTIUM_TOOL\SCHEMATICS_PARTS\MS_DISCRETE_Library.schlib; Mfr_name: PANASONIC-ECG; Mfr_part_number: ERJ-2RKF1003X; Mistral Part No: 110009030187-R; Package: 0402; Part_type: RESISTORS\FIXED; Project: J32; RoHS: RoHS; Temperature: -55°C+155°C; Tolerance: 1%; Voltage: NA; Wattage: 1/10W; Weight: 0.8mg; Datasheet: Y:\MIS_DATABASE\DATASHEETS\RESISTORS\PAN-ERJSER_NOV17.PDF
R425 = RESISTOR: RES 0E 1/20W JUMPER 0201; Chkd/date: VASANTHA/061216; Crtd /date: MAZHAR/040505; Custom_Duty: 15%; Customs_HS_Code: 85332119; Distributor_name: DIGIKEY; Distributor_part_number: P0.0AGCT-ND; Footprint Path: Y:\MIS_DATABASE\Library\ALTIUM_TOOL\PCB_FOOTPRINTS\Altium_Footprint_Lib.PcbLib; Height: 0.26MM; Library Path: Y:\MIS_DATABASE\Library\ALTIUM_TOOL\SCHEMATICS_PARTS\MS_DISCRETE_Library.schlib; Mfr_name: PANASONIC-ECG; Mfr_part_number: ERJ-1GE0R00C; Mistral Part No: 110009030078-R; Package: 0201; Part_type: RESISTORS\FIXED; Project: HS100RD; RoHS: RoHS; Temperature: -55°C+125°C; Tolerance: NA; Voltage: NA; Wattage: 1/20W; Weight: 0.15mg; Datasheet: Y:\MIS_DATABASE\DATASHEETS\RESISTORS\PAN-ERJXGE-FEB06.PDF
R428 = RESISTOR: RES 10K 1/20W 1% 0201; Chkd/date: VASANTHA/270117; Crtd /date: MANIRAJA/270117; Custom_Duty: 15%; Customs_HS_Code: 85332119; Distributor_name: DIGIKEY; Distributor_part_number: 311-10.0KMCT-ND; Footprint Path: Y:\MIS_DATABASE\Library\ALTIUM_TOOL\PCB_FOOTPRINTS\Altium_Footprint_Lib.PcbLib; Height: 0.26MM; Library Path: Y:\MIS_DATABASE\Library\ALTIUM_TOOL\SCHEMATICS_PARTS\MS_DISCRETE_Library.schlib; Mfr_name: YAGEO AMERICA; Mfr_part_number: RC0201FR-0710KL; Mistral Part No: 110011040018-R; Package: 0201; Part_type: RESISTORS\FIXED; Project: GOLDEN-I LITE; RoHS: RoHS; Temperature: -55°C+125°C; Tolerance: 1%; Voltage: NA; Wattage: 1/20W; Weight: 0.17mg; Datasheet: Y:\MIS_DATABASE\DATASHEETS\RESISTORS\RCXXXXL-SER_MAR18.PDF
R445 = RESISTOR: RES 100K 1/20W 1% 0201; Chkd/date: MANIRAJA/120520; Crtd /date: ALVY/120520; Custom_Duty: 15%; Customs_HS_Code: 85332119; Distributor_name: DIGIKEY; Distributor_part_number: 311-100KMCT-ND; Footprint Path: Y:\MIS_DATABASE\Library\ALTIUM_TOOL\PCB_FOOTPRINTS\Altium_Footprint_Lib.PcbLib; Height: 0.26MM; Library Path: Y:\MIS_DATABASE\Library\ALTIUM_TOOL\SCHEMATICS_PARTS\MS_DISCRETE_Library.schlib; Mfr_name: YAGEO AMERICA; Mfr_part_number: RC0201FR-07100KL; Mistral Part No: 110009060005-R; Package: 0201; Part_type: RESISTORS\FIXED; Project: SD865_NANOSOM; RoHS: RoHS; Temperature: -55°C+125°C; Tolerance: 1%; Voltage: NA; Wattage: 1/20W; Weight: 9mg; Datasheet: Y:\MIS_DATABASE\DATASHEETS\RESISTORS\RCXXXXL-SER_MAR18.PDF
R447 = RESISTOR: RES 0E 1/16W JUMPER 0402; Chkd/date: VASANTHA/201216; Crtd /date: MUDDU/190810; Custom_Duty: 15%; Customs_HS_Code: 85332119; Distributor_name: DIGIKEY; Distributor_part_number: 541-0.0JCT-ND; Footprint Path: Y:\MIS_DATABASE\Library\ALTIUM_TOOL\PCB_FOOTPRINTS\Altium_Footprint_Lib.PcbLib; Height: 0.40MM; Library Path: Y:\MIS_DATABASE\Library\ALTIUM_TOOL\SCHEMATICS_PARTS\MS_DISCRETE_Library.schlib; Mfr_name: VISHAY; Mfr_part_number: CRCW04020000Z0ED; Mistral Part No: 110010080019-R; Package: 0402; Part_type: RESISTORS\FIXED; Project: PB_BUGBASE; RoHS: RoHS; Temperature: -55°C+155°C; Tolerance: NA; Voltage: NA; Wattage: 1/16W; Weight: 0.65mg; Datasheet: Y:\MIS_DATABASE\DATASHEETS\RESISTORS\CRCW0603.PDF
R449 = RESISTOR: RES 1K 1/10W 1% 0402; Chkd/date: VASANTHA/281216; Crtd /date: MAZHAR/150506; Custom_Duty: 15%; Customs_HS_Code: 85332119; Distributor_name: DIGIKEY; Distributor_part_number: P1.00KLCT-ND; Footprint Path: Y:\MIS_DATABASE\Library\ALTIUM_TOOL\PCB_FOOTPRINTS\Altium_Footprint_Lib.PcbLib; Height: 0.40MM; Library Path: Y:\MIS_DATABASE\Library\ALTIUM_TOOL\SCHEMATICS_PARTS\MS_DISCRETE_Library.schlib; Mfr_name: PANASONIC-ECG; Mfr_part_number: ERJ-2RKF1001X; Mistral Part No: 110009030411-R; Package: 0402; Part_type: RESISTORS\FIXED; Project: VOCERA; RoHS: RoHS; Temperature: -55°C+155°C; Tolerance: 1%; Voltage: NA; Wattage: 1/10W; Weight: 0.8mg; Datasheet: Y:\MIS_DATABASE\DATASHEETS\RESISTORS\PAN-ERJSER_NOV17.PDF
R468 R485 = RESISTOR: RES 10K 1/20W 1% 0201; Chkd/date: MANIRAJA/260618; Crtd /date: ALVY/260618; Custom_Duty: 15%; Customs_HS_Code: 85332119; Distributor_name: DIGIKEY; Distributor_part_number: 541-10.0KABCT-ND; Footprint Path: Y:\MIS_DATABASE\Library\ALTIUM_TOOL\PCB_FOOTPRINTS\Altium_Footprint_Lib.PcbLib; Height: 0.28MM; Library Path: Y:\MIS_DATABASE\Library\ALTIUM_TOOL\SCHEMATICS_PARTS\MS_DISCRETE_Library.schlib; Mfr_name: VISHAY; Mfr_part_number: CRCW020110K0FNED; Mistral Part No: 110018060032-R; Package: 0201; Part_type: RESISTORS\FIXED; Project: NEXTNAV_LPRX_BOARD; RoHS: RoHS; Temperature: -55°C+155°C; Tolerance: 1%; Voltage: NA; Wattage: 1/20W; Weight: 0.17mg; Datasheet: Y:\MIS_DATABASE\DATASHEETS\RESISTORS\CRCW0201.PDF
TP58 = TESTPOINT: TESTPOINT CIR 20 SMD; Chkd/date: SHREESHAIL/171006; Crtd /date: MAZHAR/171006; Custom_Duty: NA; Customs_HS_Code: NA; Distributor_name: NA; Distributor_part_number: NA; Footprint Path: Y:\MIS_DATABASE\Library\ALTIUM_TOOL\PCB_FOOTPRINTS\Altium_Footprint_Lib.PcbLib; Height: NA; Library Path: Y:\MIS_DATABASE\Library\ALTIUM_TOOL\SCHEMATICS_PARTS\MS_DISCRETE_Library.schlib; MECHANICAL 3D STEP FILE: NA; Mfr_name: LOCAL; Mistral Part No: NA; Package: SMD; Project: BT MODULE_CSRBC04; RoHS: NA; Temperature: NA; Tolerance: NA; Voltage: NA; Wattage: NA; Weight: NA; Datasheet: NA
U34 = W25Q80BWSNIG_SOIC8: IC SERIAL FLASH MEMORY SOIC8; Chkd/date: VASANTHA/150217; Crtd /date: MANIRAJA/150217; Custom_Duty: 15%; Customs_HS_Code: 85423100; Distributor_name: DIGIKEY; Distributor_part_number: W25Q80DVSNIG CT-ND; Height: 1.75MM; Mfr_name: WINBOND; Mfr_part_number: W25Q80DVSNIG-TR; Mistral Part No: 141117020010-R; Package: SOIC8; Part_type: ICS\DIGITAL\MEMORY; Project: SD820_NANO_SOM; RoHS: RoHS; Temperature: -40°C+85°C; Tolerance: NA; Voltage: NA; Wattage: NA; Weight: NA; Datasheet: Y:\MIS_DATABASE\DATASHEETS\ICS\MEMORY\W25Q80DVSS.PDF
U90 = TPS65988DJ_VQFN56: IC 2-PORT USB TYPE-C AND USB PD CONTROLLER WITH INTEGRATED POWER SWITCH VQFN56; Chkd/date: MANIRAJA/290721; Crtd /date: ALVY/280721; Custom_Duty: 15%; Customs_HS_Code: 85423100; Distributor_name: DIGIKEY; Distributor_part_number: 296-52068-1-ND; Footprint Path: Y:\MIS_DATABASE\Library\ALTIUM_TOOL\PCB_FOOTPRINTS\Altium_Footprint_Lib.PcbLib; Height: 1.00MM; Library Path: Y:\MIS_DATABASE\Library\ALTIUM_TOOL\SCHEMATICS_PARTS\MS_MISCPOWER_Library.schlib; Mfr_name: TEXAS INSTRUMENTS; Mistral Part No: 142021070017-R; Package: VQFN56; Part_type: ICS\POWER\MANAGEMENT; Project: TI_AM62x_SKEVM; RoHS: RoHS; Temperature: -10°C+75°C; Tolerance: NA; Voltage: NA; Wattage: NA; Weight: 127.6mg; Datasheet: Y:\MIS_DATABASE\DATASHEETS\ICS\POWER\TPS65988DHRSHR.PDF
U91 = TVS2200_WSON6: IC 22V FLAT-CLAMP SURGE PROTECTION DEVICE WSON6; Chkd/date: MANIRAJA/011021; Crtd /date: ALVY/011021; Custom_Duty: 15%; Customs_HS_Code: 85423100; Distributor_name: DIGIKEY; Distributor_part_number: 296-52187-1-ND; Footprint Path: Y:\MIS_DATABASE\Library\ALTIUM_TOOL\PCB_FOOTPRINTS\Altium_Footprint_Lib.PcbLib; Height: 0.80MM; Library Path: Y:\MIS_DATABASE\Library\ALTIUM_TOOL\SCHEMATICS_PARTS\MS_MISCPOWER_Library.schlib; Mfr_name: TEXAS INSTRUMENTS; Mistral Part No: 142021100001-R; Package: WSON6; Part_type: ICS\POWER; Project: TI_AM62x SKEVM_BRD; RoHS: RoHS; Temperature: -40°C+125°C; Tolerance: NA; Voltage: NA; Wattage: NA; Weight: 12mg; Datasheet: Y:\MIS_DATABASE\DATASHEETS\ICS\POWER\TVS2200.PDF

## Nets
DGND: C105.2 C113.2 C116.2 C117.2 C118.2 C120.2 C121.1 C122.2 C123.1 C126.2 C128.2 C130.2 C131.2 C132.2 C410.2 C415.2 C417.2 C423.2 C428.2 C436.2 C449.2 C450.2 C594.2 C595.2 C596.2 C597.2 D4.2(ANODE) D10.2(ANODE) J11.2 J11.10 J13.A1(GND) J13.A12(GND) J13.B1(GND) J13.B12(GND) LD4.1(CATHODE) Q9.4(S1) Q9.7(S2) R157.2 R413.1 R424.2 R429.2 R445.2 R453.2 U34.4(GND) U90.20(GND) U90.51(GND) U90.59(GND) U91.1(GND) U91.2(GND) U91.3(GND) U91.7(GND) ; also on sheet 11 12 13 14 15 16 17 18 19 20 21 22 23 24 25 26 27 28 29 30 31 32 33 34 35 36 37 38 39 40 41 42 43 44
VBUS_TYPEC1: C118.1 C415.1 C417.1 C594.1 C595.1 C596.1 C597.1 J13.A4(VBUS1) J13.A9(VBUS2) J13.B4(VBUS3) J13.B9(VBUS4) R160.2 U90.13(VBUS1) U91.4(IN1) U91.5(IN2) U91.6(IN3)
VBUS_TYPEC2: C126.1 C423.1 C428.1 C449.1 C450.1 C455.1 Q11.4(D1) Q11.7(D2) R485.1 U90.3(VBUS2) ; also on sheet 35 36
VCC_3V3_SYS: R167.1 ; also on sheet 11 13 14 18 19 20 22 23 24 26 27 29 30 31 33 34 35 36 37 38 39 40 41 42 43
VCC_5V0: C436.1 C444.1 Q10.4(D1) Q10.7(D2) R447.1 R468.1 ; also on sheet 11 15 33 35 38 41
ADCIN1: R428.2 R429.1 U90.6(ADCIN1)
ADCIN2: R424.1 R425.2 U90.10(ADCIN2)
DRAIN1: U90.8(DRAIN1_1) U90.15(DRAIN1_2) U90.19(DRAIN1_3) U90.58(DRAIN1_4)
DRAIN2: U90.7(DRAIN2_1) U90.52(DRAIN2_2) U90.56(DRAIN2_3) U90.57(DRAIN2_4)
LDO_1V8: C122.1 U90.35(LDO_1V8)
LDO_3V3: C105.1 C121.2 R142.1 R145.1 R146.1 R147.1 R158.1 R161.1 R412.1 R414.1 R415.1 R419.1 R425.1 R428.1 U34.8(VCC) U90.9(LDO_3V3) ; also on sheet 13
P2_PP_EXT_ENABLE: R449.1 U90.49(GPIO17/PP_EXT2)
PD_GPIO0: R416.2 U90.16(GPIO0)
PD_GPIO2: TP58.1(TP) U90.18(GPIO2)
PD_HRESET: R445.1 U90.44(HRESET)
PD_I2C_IRQ: R167.2 R169.1 ; also on sheet 40
PD_M_I2C3_IRQ: R412.2 U90.23(~{I2C3_IRQ}/GPIO7)
PD_M_I2C3_SCL: R161.2 R395.1 U90.21(I2C3_SCL/GPIO5)
PD_M_I2C3_SDA: R158.2 R396.1 U90.22(I2C3_SDA/GPIO6)
PD_MS_I2C1_IRQ: R419.2 U90.29(~{I2C1_IRQ})
PD_MS_I2C1_SCL: R393.1 R415.2 U90.27(I2C1_SCL)
PD_MS_I2C1_SDA: R394.1 R414.2 U90.28(I2C1_SDA)
PD_S_I2C2_IRQ: R169.2 U90.34(~{I2C2_IRQ})
PD_S_I2C2_SCL: R421.2 U90.32(I2C2_SCL)
PD_S_I2C2_SDA: R422.2 U90.33(I2C2_SDA)
PD_SPI_CLK: J11.7 R436.2 U34.6(CLK)
PD_SPI_MISO: J11.5 R146.2 R426.2 U34.2(DO(IO1))
PD_SPI_MOSI: J11.8 R431.2 U34.5(DI(IO0))
PD_SPI_SS: J11.9 R147.2 R439.2 U34.1(~{CS})
PD_VIN_3V3: C123.2 U90.5(VIN_3V3)
PP1_CABLE: C117.1 U90.25(PP1_CABLE)
PP2_CABLE: R447.2 U90.46(PP2_CABLE)
SoC_I2C0_SCL: R421.1 ; also on sheet 13 22 33 42
SoC_I2C0_SDA: R422.1 ; also on sheet 13 22 33 42
SoC_USB0_DRVVBUS: R416.1 R446.1 ; also on sheet 35
SPI_HOLDn: R145.2 U34.7(~{HOLD}(IO3))
SPI_WPn: R142.2 U34.3(~{WP}(IO2))
USB_TYPEC1_EARTH: C410.1 J13.SH1 J13.SH2 J13.SH3 J13.SH4 R157.1
USBC_CONN1_CC1: C113.1 D4.1(CATHODE) J13.A5(CC1) U90.24(C1_CC1)
USBC_CONN1_CC2: C116.1 D10.1(CATHODE) J13.B5(CC2) U90.26(C1_CC2)
USBC_CONN2_CC1: C131.1 U90.45(C2_CC1) ; also on sheet 36
USBC_CONN2_CC2: C130.1 U90.47(C2_CC2) ; also on sheet 36
VMAIN: C120.1 C128.1 C132.1 U90.1(PP_HV2) U90.11(PP_HV1) ; also on sheet 11 12 26
N17370891: R413.2 U90.17(GPIO1)
N17824845: R426.1 U90.36(SPI_MISO/GPIO8)
N17824852: R431.1 U90.37(SPI_MOSI/GPIO9)
N17824859: R436.1 U90.38(SPI_CLK/GPIO10)
N17824866: R439.1 U90.39(~{SPI_SS}/GPIO11)
N17827086: J11.1 R393.2 R395.2
N17827089: J11.3 R394.2 R396.2
N17849698: C445.1 Q10.1(S1) Q10.2(S2) Q10.5(S3) Q10.6(S4) Q10.8(S5) Q11.1(S1) Q11.2(S2) Q11.5(S3) Q11.6(S4) Q11.8(S5) R475.1
N17850096: C444.2 C445.2 C455.2 Q10.3(G) Q11.3(G) R467.1 R468.2 R475.2 R485.2
N17935978: Q9.3(G) R446.2 R449.2 R453.1
N17936309: Q9.1(D1) Q9.2(D2) Q9.5(D3) Q9.6(D4) Q9.8(D5) R467.2
N22682365: LD4.2(ANODE) R160.1

Not connected (* = marked no-connect by the designer): J11 4* 6*; J13 A2(TX1+)* A3(TX1-)* A6(D+_1)* A7(D-_1)* A8(SBU1)* A10(RX2-)* A11(RX2+)* B2(TX2+)* B3(TX2-)* B6(D+_2)* B7(D-_2)* B8(SBU2)* B10(RX1-)* B11(RX1+)*; U90 30(HPD1/GPIO3)* 31(HPD2/GPIO4)* 40(GPIO12)* 41(GPIO13)* 42(GPIO14/PWM)* 43(GPIO15/PWM)* 48(GPIO16/PP_EXT1)* 50(C1_USB_P/GPIO18)* 53(C1_USB_N/GPIO19)* 54(C2_USB_P/GPIO20)* 55(C2_USB_N/GPIO21)*

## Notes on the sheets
sheet 1
- LINKS TO KEY COLLATERALS
- Hardware Design Guide :
- https://www.ti.com/lit/an/sprad85/sprad85.pdf
- Schematic Design guidelines combined for Sitara processor families :
- https://www.ti.com/lit/an/sprad21d/sprad21d.pdf
- PMIC Power Solutions Application Note :
- https://www.ti.com/lit/po/slvt204/slvt204.pdf
- DDR Board Design and Layout Guidelines :
- https://www.ti.com/lit/an/sprad66a/sprad66a.pdf
- SKs (Starter Kits) for reference :
  SK-AM62B, SK-AM62B-P1, SK-AM62-LP, SK-AM62-SIP, SK-AM62A-LP, SK-AM62P-LP
- LINKS TO KEY FAQs
- https://e2e.ti.com/support/processors-group/processors/f/processors-forum/1203305/faq-am62a7-and-am62a7-q1-custom-board-hardware-design-
  collaterals-to-get-started
- https://e2e.ti.com/support/processors-group/processors/f/processors-forum/1203441/faq-am62a3-and-am62a3-q1-custom-board-hardware-design-
  collaterals-to-get-started
- https://e2e.ti.com/support/processors-group/processors/f/processors-forum/1306030/faq-am62p-am62p-q1-custom-board-hardware-design--
  -faqs-related-to-processor-collaterals-functioning-peripherals-interface-and-starter-kit
- https://e2e.ti.com/support/processors-group/processors/f/processors-forum/1340905/faq-am62a7-am62a7-q1-am62a3-am62a3-q1---custom-board
  -hardware-design---guidelines-for-reuse-of-sk-am62a-lp-schematics
- https://e2e.ti.com/support/processors-group/processors/f/processors-forum/1347063/faq-am62a7-and-am62a7-q1-am62a3-and-am62a3-q1---
  custom-board-hardware-design---design-and-review-notes-for-reuse-of-sk-am62a-lp-schematics
- https://e2e.ti.com/support/processors-group/processors/f/processors-forum/1280753/faq-am62a7-am62a7-q1-am62a3-am62a3-q1-custom-board-
  hardware-design---faqs-related-to-processor-collaterals-functioning-peripherals-interface-and-starter-kit
sheet 2
- AM62A7 / AM62A3 LOW POWER STARTER KIT SK (EVM)
                         WITH TPS65931211-Q1 PMIC
- TABLE OF CONTENTS
- Revision Number
- PAGE
- CONTENTS
- PAGE
- CONTENTS
- REV
- B
- 01
- TABLE OF CONTENTS
- 24
- CPSW3G  RGMII_2 ETHERNET PHY
- VER
- 0.3
- 02
- REVISION HISTORY
- 25
- SOC MAC INTERFACE, CLOCK BUFFER FOR SOC AND ETHERNET PHYS
- 03
- LINKS TO KEY COLLATERALS AND FAQs
- 26
- TEST AUTOMATION
- 04
- BLOCK DIAGRAM SK-AM62A-LP
- 27
- BOOT MODE CONFIGURATION BUFFERS, RESISTOR DIVIDERS AND DIP SWITCHES
- 05
- BLOCK DIAGRAM XDS110 DEBUGGER
- 28
- XDS110 DEBUGGER
- 06
- POWER ARCHITECTURE BLOCK DIAGRAM
- 29
- SOC JTAG INTERFACE & JTAG BUFFERS
- 07
- POWER-UP AND POWER-DOWN SEQUENCE
- 30
- JTAG 20 PIN cTI CONNECTOR AND BUFFERS
- 08
- I2C TREE
- 31
- FT4232 UART TO USB BRIDGE
- 09
- GPIO MAPPING TABLE
- 32
- SOC WKUP AND SOC GPMC INTERFACE
- 10
- USB TYPE-C PD CONTROLLER AND  POWER SUPPLY
- 33
- USER EXPANSION CONNECTOR
- 11
- PERIPHERAL POWER SUPPLIES - 1
- 34
- SOC-MCU DOMAIN IO and OSC0 AND SOC-MCU IO HEADER
- 12
- PERIPHERAL POWER SUPPLIES - 2
- 35
- SOC USB INTERFACE, USB1 TYPE A CONNECTOR, VBUS DIVIDER AND POWER SWITCH
- 13
- SOC POWER SUPPLIES - PMIC BASED WITH SOC CURRENT MEASUREMENT SHUNTS
- 36
- USB0 TYPE-C DRP & USER TEST LEDs
- 14
- CURRENT MONITORING DEVICES
- 37
- SoC UART1 FET SWITCH & BUFFER
- 15
- SOC SUPPLY RAILS AND POWER SUPPLIES
- 38
- SOC CSI INTERFACE,  BIDIRECTIONAL PASSIVE SWITCH AND CAMERA CONNECTOR
- 16
- SOC POWER SUPPLIES - DECAPS & SOC GROUND VSS
- 39
- AUDIO CODEC
- 17
- SOC DDRSS AND LPDDR4 MEMORY DEVICE INTERFACE
- 40
- IO EXPANDER AND MCASP1 FET SWITCH AND BUFFER
- 18
- M.2 INTERFACE AND CONNECTOR
- 41
- SOC DPI INTERFACE, DPI TO HDMI TRANSMITTER INTERFACE
- 19
- SOC MMC0..2 INTERFACE, eMMC FLASH AND eMMC FLASH RESET
- 42
- SOC RESETs AND IOs, AND EXTERNAL LVCMOS CLOCK (OSCILLATOR)
- 20
- SD CARD - LOAD SWITCH, LOAD SWITCH RESET LOGIC AND DATA INTERFACE
- 43
- SOC RESETS - COLD AND WARM
- 21
- SOC OSPI/QSPI INTERFACE, OSPI FLASH AND OSPI FLASH RESET
- 44
- EXTERNAL SWITCH FOR CAN FD WKUP
- 22
- BOARD ID EEPROM & DIGITAL TEMPERATURE SENSORS
- 45
- ASSEMBLY NOTES AND MOUNTING HARDWARE
- 23
- CPSW3G RGMII_1 ETHERNET PHY
- D-Note :-
- SK/EVM is a device evaluation board or platform. The SK/EVM is not a reference design. In some cases the EVM implementation may deviate from the optimum
  solution to provide a better customer experience or provide flexibility for customers to be able to validate the SOC functionality. TI expects and
  recommends customers to carefully review and follow all requirements defined in the datasheet, silicon errata, and TRM when designing their custom board.
  The information found in the datasheet should always take precedence over the SK/EVM implementation.
- R-Note :-
- * Verify the DNI components configuration with respect to the SK schematics (Use PDF) after completion of board design before board assembly
  * A standard 5% tolerance resistor can be used for most of the series and parallel pull resistor
  * Be sure to read through all the D-Notes (Design notes), R-Notes (Review notes) and CAD notes during board design and before start of board build.
  (Refer FAQs listed for additional details)
- Indicates circuit level change
- C
- Indicates that the value of the component has been updated.
- V
sheet 3
- REVISION HISTORY
- VER #
- DATE
- DESCRIPTION OF CHANGES
- AUTHOR
- REVIEWED  BY
- APPROVED  BY
- 0.1
- 03 JUNE 2026
- Drafted from "PROC135EA_SCH" document.
- Mistral Design Team
- Pandiyarajan
- Ajit MB
- 0.2
- 08 JUNE 2026
- Below components have been updated based on TI review comments checklist:
  - U30 part number has been changed to TPS2051BD and the corresponding circuit has been updated
  - U129 and the corresponding circuit have been added for ESD protection of USB data lines
  - Replaced U20 with a dual-channel load switch of Part number TPS22996HQDYCRQ1
  - Added RC filter of value 62E and 47pF to WKUP_I2C0_SCL, WKUP_I2C0_SDA, MCU_I2C0_SCL, MCU_I2C0_SDA and EXTINTn signals
  - Added a series resistor of value 22E R782, R748 and R761 to the nets SOC_SPI2_CLK, MCU_SPI0_CLK and SoC_SPI0_CLK respectively
  - Added a series resistor of value 47E R757, R758 and R759, R760 to SoC_I2C0_SCL, SoC_I2C0_SDA, SoC_I2C1_SCL and SoC_I2C1_SDA
  respectively
  - Tolerance value of R160, R475, R467 has been changed from 1% to 5%
  - Tolerance value of C241, C222, C235, C220, C285, C231, C223, C264, C287 from 20% to 10%
  - Pull-ups of OSPI, MMC0, MMC1 and MMC2 have been changed from 10k to 47k
  - Added four 0.01µF capacitors each to VBUS_TYPEC1 and VBUS_TYPEC2 respectively.
  - Changed VMON_VSYS monitoring voltage from VCC_3V3_MAIN to VCC_5V0
  - Shifted all the current sense resistors to the PMIC page
  - Added 0E series resistor to all of the GPIO Reset signals that are connected to eMMC, OSPI, SD Card, HDMI, Audio CODEC, RGMII interfaces
  - Added and updated D-Notes
- Mistral Design Team
- Pandiyarajan
- Ajit MB
- 0.3
- 25 JUNE 2026
- - Added R792 series 0E Resistor to the SoC Pin PMIC_LPM_EN0
  - Updated D-Notes
- Mistral Design Team
- Pandiyarajan
- Ajit MB
sheet 4
- BLOCK DIAGRAM SK-AM62A-LP
sheet 5
- BLOCK DIAGRAM_XDS110
sheet 6
- POWER BLOCK DGM
sheet 7
- POWER SEQUENCE
sheet 8
- I2C TREE
sheet 9
- GPIO MAPPING TABLE
sheet 10
- D-Note:
  Refer to the SK/EVM user's guide for the recommended power adapters.
  Using the recommended adapter is recommended for proper functioning of SK/EVM
  Reference Document:
  EVM User's Guide : https://www.ti.com/lit/pdf/SPRUJ40
  Reference section : Power Requirement
- USB TYPE-C PD CONTROLLER AND POWER SUPPLY
- Silk: TYPE-C PWR
- C
- C
- TYPE-C DUAL PD CONTROLLER
- C
- C
- POWER INDICATION LED: VBUS_TYPEC1
- BP_NoWait
  Safe Configuration
- V
- EXTERNAL POWER PATH FOR SOURCING, 5V/0.5A
- D-Note :-
  Refer AM62P implementation
  for adding the capacitors
- I2C Slave
   Address
- Port1
- Port2
- I2C2(Default)
- 0x38
- 0x3F
- I2C1
- 0x20
- 0x24
- V
- SPI EEPROM & PROGRAMMING HEADER
- V
